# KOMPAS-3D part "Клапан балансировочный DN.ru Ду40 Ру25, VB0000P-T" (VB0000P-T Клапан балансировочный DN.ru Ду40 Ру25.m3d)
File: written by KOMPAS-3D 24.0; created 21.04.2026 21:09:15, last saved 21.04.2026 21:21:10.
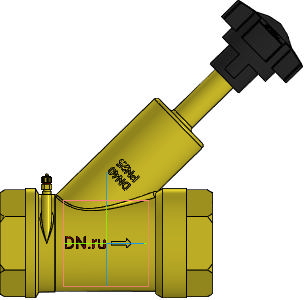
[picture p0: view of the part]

Document properties: Автор: DN.ru; Полное имя файла: E:\Работа\Зайцев\АУТСОРС\Диман\Балансировка\VB0000P-T Клапан балансировочный DN.ru Ду15-50 Ру25\DN40\VB0000P-T Клапан балансировочный DN.ru Ду40 Ру25.m3d

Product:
- Part/product: Клапан балансировочный DN.ru Ду40 Ру25  | designation VB0000P-T
    Масса: 1.2
    Раздел спецификации: Прочие изделия
    Примечание: D080-01179

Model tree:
1. Операция без истории:1

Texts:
  VB0000P-T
